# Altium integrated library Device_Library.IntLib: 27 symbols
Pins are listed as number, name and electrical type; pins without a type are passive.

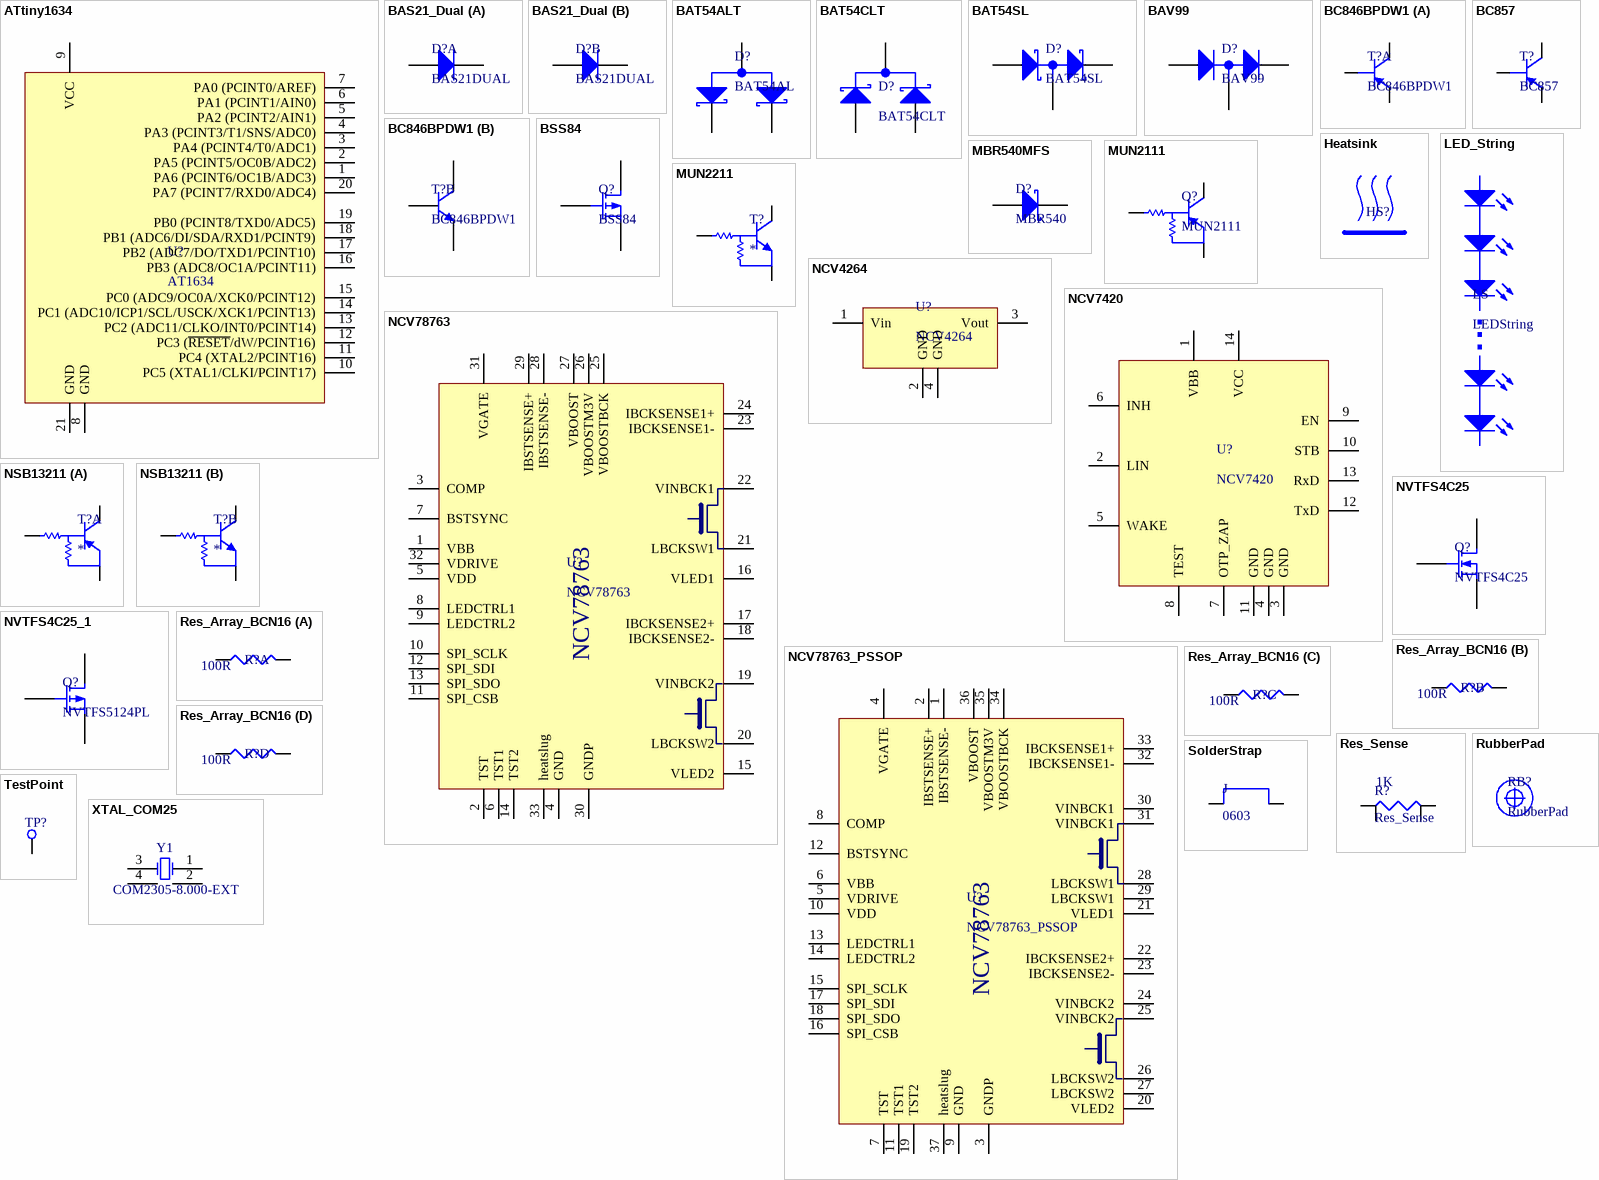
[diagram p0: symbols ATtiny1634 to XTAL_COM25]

## ATtiny1634
designator U?, comment AT1634
footprint 20M1_N (QFN, 20-Leads, Body 4x4mm, Pitch 0.5mm, IPC Medium Density)
pins: 1 PA6 (PCINT6/OC1B/ADC3), 2 PA5 (PCINT5/OC0B/ADC2), 3 PA4 (PCINT4/T0/ADC1), 4 PA3 (PCINT3/T1/SNS/ADC0), 5 PA2 (PCINT2/AIN1), 6 PA1 (PCINT1/AIN0), 7 PA0 (PCINT0/AREF), 8 GND, 9 VCC, 10 PC5 (XTAL1/CLKI/PCINT17), 11 PC4 (XTAL2/PCINT16), 12 PC3 (~{RESET}/dW/PCINT16), 13 PC2 (ADC11/CLKO/INT0/PCINT14), 14 PC1 (ADC10/ICP1/SCL/USCK/XCK1/PCINT13), 15 PC0 (ADC9/OC0A/XCK0/PCINT12), 16 PB3 (ADC8/OC1A/PCINT11), 17 PB2 (ADC7/DO/TXD1/PCINT10), 18 PB1 (ADC6/DI/SDA/RXD1/PCINT9), 19 PB0 (PCINT8/TXD0/ADC5), 20 PA7 (PCINT7/RXD0/ADC4), 21 GND

## BAS21_Dual
designator D?, comment BAS21DUAL
footprint SC-88A (SOT353, 5-Leads, Body 2x1.3mm, Pitch 0.65mm, Lead Span 2.1mm, IPC Medium Density)
part A pins: 1 A, 5 K
part B pins: 3 A, 4 K

## BAT54ALT
designator D?, comment BAT54AL
footprint SOT23 (SOT23, 3-Leads, Body 2.90x2.37mm, Pitch 0.95mm, IPC Medium Density)
pins: 1 A, 2 K, 3 A/K

## BAT54CLT
designator D?
footprint SOT23 (SOT23, 3-Leads, Body 2.90x2.37mm, Pitch 0.95mm, IPC Medium Density)
pins: 1 A, 2 K, 3 A/K

## BAT54SL
designator D?
footprint SOT23 (SOT23, 3-Leads, Body 2.90x2.37mm, Pitch 0.95mm, IPC Medium Density)
pins: 1 A, 2 K, 3 A/K

## BAV99
designator D?
footprint SOT23 (SOT23, 3-Leads, Body 2.90x2.37mm, Pitch 0.95mm, IPC Medium Density)
pins: 1 A, 2 K, 3 A/K

## BC846BPDW1
designator T?
footprint SOT-363
part A pins: 3 PNP_C, 4 PNP_E, 5 PNP_B
part B pins: 1 NPN_E, 2 NPN_B, 6 NPN_C

## BC857
designator T?
footprint SOT23 (SOT23, 3-Leads, Body 2.90x2.37mm, Pitch 0.95mm, IPC Medium Density)
simulation model Qbc856alt1g (Model Description)
pins: 1 B, 2 E, 3 C

## BSS84
designator Q?
simulation model bss84lt1 (Model Description)
footprint SOT23 (SOT23, 3-Leads, Body 2.90x2.37mm, Pitch 0.95mm, IPC Medium Density)
pins: 1 G, 2 S, 3 D

## Heatsink
designator HS?  (value not drawn)  (mechanical)
Heatsink

## LED_String
designator LS, comment LEDString  (mechanical)

## MBR540MFS
designator D?, comment MBR540
footprint SO8FL_3pin
simulation model Dmbr540mfs (Model Description)
pins: 1 A, 3 K

## MUN2111
designator Q?
footprint SOT23 (SOT23, 3-Leads, Body 2.90x2.37mm, Pitch 0.95mm, IPC Medium Density)
simulation model mun2111t1 (Model Description)
pins: 1 B, 2 E, 3 C

## MUN2211
designator T?
footprint SOT23 (SOT23, 3-Leads, Body 2.90x2.37mm, Pitch 0.95mm, IPC Medium Density)
simulation model mun2211t1
pins: 1 B, 2 E, 3 C

## NCV4264
designator U?
footprint SOT223_N (SOT223, 4-Leads, Body 6.5x3.5mm, Pitch 2.3mm, Lead Span 7mm, IPC Medium Density)
pins: 1 Vin, 2 GND, 3 Vout, 4 GND

## NCV7420
designator U?
footprint SOIC-14 (14-Pin Small Outline Integrated Circuit 1.27 mm Pitch, IPC Medium Density)
pins: 1 VBB, 2 LIN, 3 GND, 4 GND, 5 WAKE, 6 INH, 7 OTP_ZAP, 8 TEST, 9 EN, 10 STB, 11 GND, 12 TxD, 13 RxD, 14 VCC

## NCV78763
designator U?
NCV78763 Power Ballast and Dual LED Driver for Automotive Front Lighting
footprint QFN32_0_5MM (QFN, 32-Leads, Body 5x5mm, Pitch 0.5mm, IPC Medium Density)
pins: 1 VBB, 2 TST, 3 COMP, 4 GND, 5 VDD, 6 TST1, 7 BSTSYNC, 8 LEDCTRL1, 9 LEDCTRL2, 10 SPI_SCLK, 11 SPI_CSB, 12 SPI_SDI, 13 SPI_SDO, 14 TST2, 15 VLED2, 16 VLED1, 17 IBCKSENSE2+, 18 IBCKSENSE2-, 19 VINBCK2, 20 LBCKSW2, 21 LBCKSW1, 22 VINBCK1, 23 IBCKSENSE1-, 24 IBCKSENSE1+, 25 VBOOSTBCK, 26 VBOOSTM3V, 27 VBOOST, 28 IBSTSENSE-, 29 IBSTSENSE+, 30 GNDP, 31 VGATE, 32 VDRIVE, 33 heatslug

## NCV78763_PSSOP
designator U?
NCV78763 Power Ballast and Dual LED Driver for Automotive Front Lighting
footprint SSOP50P1030X265_HS-37N (SSOP, 36-Leads, Body 10.30x7.50mm, Pitch 0.50mm, Thermal Pad 5.90.2x4.10.2mm, IPC Medium Density)
pins: 1 IBSTSENSE-, 2 IBSTSENSE+, 3 GNDP, 4 VGATE, 5 VDRIVE, 6 VBB, 7 TST, 8 COMP, 9 GND, 10 VDD, 11 TST1, 12 BSTSYNC, 13 LEDCTRL1, 14 LEDCTRL2, 15 SPI_SCLK, 16 SPI_CSB, 17 SPI_SDI, 18 SPI_SDO, 19 TST2, 20 VLED2, 21 VLED1, 22 IBCKSENSE2+, 23 IBCKSENSE2-, 24 VINBCK2, 25 VINBCK2, 26 LBCKSW2, 27 LBCKSW2, 28 LBCKSW1, 29 LBCKSW1, 30 VINBCK1, 31 VINBCK1, 32 IBCKSENSE1-, 33 IBCKSENSE1+, 34 VBOOSTBCK, 35 VBOOSTM3V, 36 VBOOST, 37 heatslug

## NSB13211
designator T?
footprint SOT-363
part A pins: 3 C1, 4 E1, 5 B1
part B pins: 1 E, 2 B, 6 C

## NVTFS4C25
designator Q?
simulation model nttfs4c25n (Model Description)
footprint U8FL
pins: D, G, S

## NVTFS4C25_1
designator Q?, comment NVTFS5124PL
P-Channel MOSFET u8FL
footprint U8FL
pins: 1 S, 2 G, 3 D

## Res_Array_BCN16
designator R?  value 100R  (hidden comment: Res_Array_BCN16)
Resistor
footprint BCN16
part A pins: 1, 8 2
part B pins: 2 1, 7 2
part C pins: 3 1, 6 2
part D pins: 4 1, 5 2

## Res_Sense
designator R?  value 1K
Resistor
simulation model RESISTOR (Resistor)
footprint 1206_RSENSE (Chip Capacitor, Body 3.2x1.6mm, IPC High Density)
pins: 1, 2, 3, 4

## RubberPad
designator RB?  (mechanical)

## SolderStrap
designator J, comment 0603
Resistor; Value: 1K
footprint SolderStrap (Solder Strap)
pins: 1, 2

## TestPoint
designator TP?, comment TP  (value not drawn)
footprint TP_1mm (Testpoint DIA 1mm)
pins: 1 TP

## XTAL_COM25
designator Y1, comment COM2305-8.000-EXT
Crystal Oscillator
footprint XTAL_COM25
footprint XTAL_MQ
pins: 1 OSC1, 2 GND1, 3 OSC2, 4 GND2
